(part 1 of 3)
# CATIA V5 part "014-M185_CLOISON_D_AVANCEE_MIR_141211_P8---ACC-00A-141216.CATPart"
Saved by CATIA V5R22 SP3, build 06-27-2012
Part number: Part3
Material "000000011370;Designation TOLE ACIER E390D 1,47MM G10/10;Nuance E390D;Norme Nuance B53 3312;": density 7820 kg/m3
Bounding box of the stored display mesh (mm): x -949.305 to -599.625, y 203.047 to 409.027, z -41.159 to 655.763
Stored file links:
  C:\Users\sys02\Desktop\piese D\014-M185_CLOISON_D_AVANCEE_MIR_141211_P8---ACC-00A-141216.CATPart
  Y:\SICA\141120_P8\Mxxx_CLOISON_D_RECULEE_MIR_141210_P8.CATPart
  G:\P8\envi\K1.BV2SR-.K3D.9675018780.01.SUP-D-TRA-FAC-BLO-AV.----0010CAT.CATPart
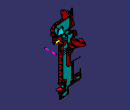
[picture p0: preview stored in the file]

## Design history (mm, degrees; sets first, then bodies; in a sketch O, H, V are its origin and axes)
StDynAnalysisRootNodeFeature1 "CATStDynAnalysisRootNodeName"
Set1 "Draft directions"
  Line1: stored without definition
  Line2: stored without definition
  DatumPoint1 to DatumPoint4
Set2 "ENV HARD"
  DatumSurface1 "--.------.---.AA37605354.--.P87-MS--------------.----0003CAT"
  DatumSurface2 "Y1.BV2SR-.R1A.981031218A.AZ.SYS-ABS-CHO-AVSUPASS.----0002CAT"
  DatumSurface3 "K1.BV2SR-.K3D.9675018780.01.SUP-D-TRA-FAC-BLO-AV.----0010CAT"
  DatumSurface4 "K686_87.BV2AM-.B12.9807801080.00.RADIATEUR-REFROIDISS.----0000CAT_PSA_140623_P8.CATPART"
  DatumSurface5 "L131_AU.P84SR-.K2E.9810619980.00.DEFLECTEUR-AIR-CENT-.----0010CAT_PSA_140826_P8"
  DatumSurface6 "L366_5155275_AU.P84SR-.R1A.981086827A.A..GRIL-SUP-PARE-CHO-AV.----0004CAT_PSA_140922_P8"
  DatumSurface7 "L624_AU.P84SR-.R1A.9811359480.00.CONARPRIAIRDPARCHOAV.----0005CAT_PSA_141013_P8.CATPART"
  DatumSurface8 "L645_AU.P84SR-.R1A.9810866880.00.ARMA-INF-PARE-CHO-AV.----0008CAT_PSA_141014_P8.CATPART"
  DatumSurface9 "L851_AU.P84SR-.K3D.9812138680.00.TRAVER-FACAD-BLOC-AV.----0006CAT_PSA_141104_P8.CATPART"
  DatumSurface10 "L851_AU.P84SR-.R1A.9810634680.00.ARMA-PARE-CHO-AV-ASS.----0004CAT_PSA_141104_P8.CATPART"
  DatumSurface11 "M150_5261904_--.------.---.AA37543391.--.P8X-FONDS-CALANDRES-.----0000CAT"
  DatumSurface12 "M150_5261913_PC AV P84_PSA_141209_P8-PART1"
  DatumSurface13 "M150_5261913_PC AV P84_PSA_141209_P8-PART2"
  DatumSurface14 "M150_5261913_PC AV P84_PSA_141209_P8-PART3"
  DatumSurface15 "L131_AU.P84SR-.K2E.9811450080.00.DEFLECTEUR-AIR-CENT-.----0007CAT_PSA_140826_P8"
  DatumSurface16 "--.------.---.AA37354130.FL.COMP-COND-SANS-CAPA-.----0001CAT"
  DatumSurface17 "K686_--.------.V5D.981046768A.A..TUYAU-REFRIGERAT-ENS.AA37308823.FL.----0000CAT_PSA_140623_P8.CATPART"
Set3 "CONSTRUCTION"
  Set4 "A FACE SOFT MATERIAL"
    Join1: Elements Fillet73
    Intersect1: ToIntersect1 Chamfer3, ToIntersect2 Join1
    Offset1: Offset Chamfer3, Length 6.5
    Intersect2: ToIntersect1 Offset1, ToIntersect2 Join1
    Line3: type PtPt, FirstPoint vertex [face of Intersect2 | face of Intersect2], SecondPoint vertex [face of Intersect2 | face of Intersect2], Start 19, End 20
    Sweep1: type Segment, GuideCrv Line3, Length1 80, Length2 20, Angle 60, DraftDirection Line1
    Line4: type PtPt, FirstPoint vertex [face of Intersect2 | face of Intersect2], SecondPoint vertex [face of Intersect2 | face of Intersect2], Start 43, End 71
    Sweep2: type Segment, GuideCrv Line4, Length1 80, Length2 20, Angle 45, DraftDirection Line1
    Trim1: Trimmed (Sweep2; Sweep1)
    Line5: type PtPt, FirstPoint vertex [face of Intersect2 | face of Intersect2], SecondPoint vertex [face of Intersect2 | face of Intersect2], Start 34, End 30
    Sweep3: type Segment, GuideCrv Line5, Length1 80, Length2 20, Angle 60, DraftDirection Line1
    Split1: ToCut Join1, Cutting Intersect2
    Extrapol1: ToExtrapol edge of Sweep2, Support Trim1, Length 50
    Split2: ToCut Sweep3, Cutting Extrapol1
    Split3: ToCut Split2, Cutting Line5
    MultiExtract1: ListOfMultiExtractConstraints (MultiExtractConstraint edge of Intersect2; MultiExtractConstraint edge of Intersect2; MultiExtractConstraint edge of Split2)
    Split4: ToCut Extrapol1, Cutting MultiExtract1
    Extrapol2: ToExtrapol edge of Sweep1, Support Split4, Length 50
    Line6: type PtPt, FirstPoint vertex [face of Intersect2 | face of Intersect2], SecondPoint vertex [face of Intersect2 | face of Intersect2], Start 24, End 42
    Sweep4: type Segment, GuideCrv Line6, Length1 80, Length2 20, Angle 30, DraftDirection Line1
    Line7: type PtPt, FirstPoint vertex [face of Intersect2 | face of Intersect2], SecondPoint vertex [face of Intersect2 | face of Intersect2], Start 28, End 37
    Sweep5: type Segment, GuideCrv Line7, Length1 80, Length2 20, Angle 60, DraftDirection Line1
    Trim2: Trimmed (Sweep4; Extrapol2)
    Trim3: Trimmed (Sweep5; Trim2)
    Line8: type PtPt, FirstPoint vertex [face of Fillet62 | face of Fillet62], SecondPoint {point type OnCurve, Support edge of Split1, Ratio 0.21}
    Sweep6: type Segment, GuideCrv Line8, Length1 80, Length2 20, Angle 60, DraftDirection Line1
    Extrapol3: ToExtrapol edge of Sweep6, Support Sweep6, Length 50
    Extrapol4: ToExtrapol edge of Sweep6, Support Extrapol3, Length 50
    Line9: type PtPt, FirstPoint {point type OnCurve, Support edge of Split1, Ratio 0.21}, SecondPoint vertex [face of DatumSurface30], Start 54, End 74
    Sweep7: type Segment, GuideCrv Line9, Length1 80, Length2 20, Angle 60, DraftDirection Line1
    Trim4: Trimmed (Sweep7; Extrapol4)
    Fillet1: radius 30, on edge [face of Sweep7 | face of Sweep6]
    Sweep8: type Segment, GuideCrv edge of Split1, Length1 120, Length2 20, Angle 60, DraftDirection Line1
    Extrapol5: ToExtrapol edge of Sweep8, Support Sweep8, Length 80
    Trim5: Trimmed (Fillet1; Extrapol5)
    Fillet2: radius 15, on edge [face of Sweep7 | face of Sweep8]
    Extrapol6: ToExtrapol edge of Sweep8, Support Fillet2, Length 20
    Sweep9: type Segment, GuideCrv edge of Split1, Length1 120, Length2 20, Angle 60, DraftDirection Line1
    Extrapol7: ToExtrapol edge of Sweep9, Support Sweep9, Length 30
    Extrapol8: ToExtrapol edge of Sweep9, Support Extrapol7, Length 30
    Trim6: Trimmed (Extrapol6; Extrapol8)
    Fillet3: radius 15, on edge [face of Sweep8 | face of Sweep9]
    Sweep10: type Segment, GuideCrv edge of Split1, Length1 80, Length2 20, Angle 60, DraftDirection Line1
    Extrapol9: ToExtrapol edge of Sweep10, Support Sweep10, Length 45
    Extrapol10: ToExtrapol edge of Sweep9, Support Fillet3, Length 30
    Trim7: Trimmed (Extrapol10; Extrapol9)
    Fillet4: radius 10, on edge [face of Sweep9 | face of Sweep10]
    Sweep11: type Segment, GuideCrv edge of Split1, Length1 80, Length2 20, Angle 60, DraftDirection Line1
    Sweep12: type Segment, GuideCrv edge of Split1, Length1 80, Length2 20, Angle 45, DraftDirection Line1
    Offset2: Offset Sweep12, Length 11
    Extrapol11: ToExtrapol edge of Sweep10, Support Fillet4, Length 45
    Extrapol12: ToExtrapol edge of Offset2, Support Offset2, Length 45
    Extrapol13: ToExtrapol edge of Offset2, Support Extrapol12, Length 45
    Split5: ToCut Extrapol11, Cutting Extrapol13
    Split6: ToCut Extrapol13, Cutting Split5
    Extrapol14: ToExtrapol edge of Sweep11, Support Sweep11, Length 45
    Split7: ToCut Extrapol14, Cutting Split6
    Split8: ToCut Split6, Cutting Split7
    Extrapol15: ToExtrapol edge of Sweep11, Support Split7, Length 45
    Sweep13: type Segment, GuideCrv edge of Split1, Length1 80, Length2 20, Angle 55, DraftDirection Line1
    Extrapol16: ToExtrapol edge of Sweep13, Support Sweep13, Length 60
    Trim8: Trimmed (Extrapol16; Extrapol15)
    Fillet5: radius 10, on edge [face of Sweep11 | face of Sweep13]
    Extrapol17: ToExtrapol edge of Sweep13, Support Fillet5, Length 60
    Sweep14: type Segment, GuideCrv edge of Split1, Length1 80, Length2 20, Angle 35, DraftDirection Line1
    Extrapol18: ToExtrapol edge of Sweep14, Support Sweep14, Length 60
    Extrapol19: ToExtrapol edge of Sweep14, Support Extrapol18, Length 60
    Trim9: Trimmed (Extrapol19; Extrapol17)
    Fillet6: radius 20, on edge [face of Sweep14 | face of Sweep13]
    Sweep15: type Segment, GuideCrv edge of Split1, Length1 80, Length2 20, Angle 60, DraftDirection Line1
    Extrapol20: ToExtrapol edge of Sweep15, Support Sweep15, Length 60
    Trim10: Trimmed (Extrapol20; Fillet6)
    Fillet7: on edge [face of Sweep15 | face of Sweep14]
    Sweep16: type Segment, GuideCrv edge of Split1, Length1 80, Length2 20, Angle 60, DraftDirection Line1
    Extrapol21: ToExtrapol edge of Sweep16, Support Sweep16, Length 60
    Extrapol22: ToExtrapol edge of Sweep16, Support Extrapol21, Length 60
    Trim11: Trimmed (Extrapol22; Split3)
    Chamfer1: length 29, second length 21, on edge [face of Sweep16 | face of Sweep3]
    Fillet8: on edge [face of Chamfer1 | face of Sweep3]
    Fillet9: on edge [face of Sweep16 | face of Chamfer1]
    Sweep17: type Segment, GuideCrv edge of Split1, Length1 80, Length2 20, Angle 45, DraftDirection Line1
    Extrapol23: ToExtrapol edge of Sweep17, Support Sweep17, Length 60
    Extrapol24: ToExtrapol edge of Sweep17, Support Extrapol23, Length 60
    Trim12: Trimmed (Fillet9; Extrapol24)
    Fillet10: on edge [face of Sweep17 | face of Sweep16]
    Sweep18: type Segment, GuideCrv edge of Split1, Length1 80, Length2 20, Angle 50, DraftDirection Line1
    Sweep19: type Segment, GuideCrv edge of Split1, Length1 80, Length2 20, Angle 50, DraftDirection Line1
    Blend1: StartLimit {blendlimit Curve edge of Sweep18}, EndLimit {blendlimit Curve edge of Sweep19}
    Join2: Elements (Blend1; Sweep19; Sweep18)
    Extrapol25: ToExtrapol edge of Sweep18, Support Join2, Length 60
    Trim13: Trimmed (Fillet10; Extrapol25)
    Fillet11: on edge [face of Sweep18 | face of Sweep17]
    Fillet12: on edge [face of Blend1 | face of Sweep18]
    Fillet13: on edge [face of Sweep19 | face of Blend1]
    Extrapol26: ToExtrapol edge of Sweep19, Support Fillet13, Length 60
    Sweep20: type Segment, GuideCrv edge of Split1, Length1 80, Length2 20, Angle 7, DraftDirection Line1
    Extrapol27: ToExtrapol edge of Sweep20, Support Sweep20, Length 60
    Extrapol28: ToExtrapol edge of Sweep20, Support Extrapol27, Length 60
    Trim14: Trimmed (Extrapol26; Extrapol28)
    Fillet14: on edge [face of Sweep19 | face of Sweep20]
    Sweep21: type Segment, GuideCrv edge of Split1, Length1 80, Length2 20, Angle 45, DraftDirection Line1
    Extrapol29: ToExtrapol edge of Sweep21, Support Sweep21, Length 60
    Extrapol30: ToExtrapol edge of Sweep21, Support Extrapol29, Length 60
    Trim15: Trimmed (Fillet14; Extrapol30)
    Fillet15: on edge [face of Sweep20 | face of Sweep21]
    Sweep22: type Segment, GuideCrv edge of Split1, Length1 80, Length2 20, Angle 45, DraftDirection Line1
    Extrapol31: ToExtrapol edge of Sweep22, Support Sweep22, Length 60
    Trim16: Trimmed (Fillet15; Extrapol31)
    Fillet16: on edge [face of Sweep21 | face of Sweep22]
    Sweep23: type Segment, GuideCrv edge of Split1, Length1 80, Length2 20, Angle 45, DraftDirection Line1
    Blend2: StartLimit {blendlimit Curve edge of Sweep23}, EndLimit {blendlimit Curve edge of Sweep22}
    Join3: Elements (Fillet16; Blend2; Sweep23)
    Fillet17: on edge [face of Sweep23 | face of Blend2]
    Fillet18: on edge [face of Blend2 | face of Sweep22]
    Extrapol32: ToExtrapol edge of Sweep23, Support Fillet18, Length 15
    Sweep24: type Segment, GuideCrv edge of Split1, Length1 80, Length2 20, Angle 7, DraftDirection Line1
    Extrapol33: ToExtrapol edge of Offset43, Support {inverselocal InverseElem Offset43}, Length 55
    Trim17: Trimmed (Extrapol32; Extrapol33)
    Fillet19: on edge [face of Sweep23 | face of Offset43]
    Extrapol34: ToExtrapol edge of Offset43, Support Fillet19, Length 10
    Offset3: Offset Sweep74, Length 0
    Sweep25: type Segment, GuideCrv edge of Split1, Length1 80, Length2 20, Angle 7, DraftDirection Line1
    Extrapol35: ToExtrapol edge of Sweep25, Support Sweep25, Length 150
    Extrapol36: ToExtrapol edge of Sweep15, Support Fillet7, Length 100
    Extrapol37: ToExtrapol edge of Sweep25, Support Extrapol35, Length 30
    Trim18: Trimmed (Extrapol37; Extrapol36)
    Extrapol38: ToExtrapol edge of Sweep25, Support Trim18, Length 30
    Trim19: Trimmed (Sweep72; Extrapol38)
    Sweep26: type Segment, GuideCrv edge of Split1, Length1 80, Length2 20, Angle 7, DraftDirection Line1
    Extrapol39: ToExtrapol edge of Sweep26, Support Sweep26, Length 100
    Trim20: Trimmed (Trim19; Extrapol39)
    Sweep27: type Segment, GuideCrv edge of Split1, Length1 80, Length2 20, Angle 30, DraftDirection Line1
    Extrapol40: ToExtrapol edge of Sweep27, Support Sweep27, Length 110
    Extrapol41: ToExtrapol edge of Sweep27, Support Extrapol40, Length 60
    Trim21: Trimmed (Trim20; Extrapol41)
    Line10: stored without definition
    Sweep28: type Segment, GuideCrv Line10, Length1 80, Length2 20, Angle 7, DraftDirection Line1
    Extrapol42: ToExtrapol edge of Offset42, Support {inverselocal InverseElem Offset42}, Length 20
    Extrapol43: ToExtrapol edge of Offset42, Support Extrapol42, Length 60
    CurvePar1: Offset edge of Offset3, Support Offset3, Offset2 0, Offset1 22
    Split9: ToCut Offset3, Cutting CurvePar1
    Trim22: Trimmed (Split9; Extrapol34)
    Trim23: Trimmed (Trim22; Extrapol43)
    Trim24: Trimmed (Trim23; Trim21)
    Extrapol44: ToExtrapol edge of Split6, Support Split8, Length 60
    Split10: ToCut Extrapol44, Cutting Join1
    Extrapol45: ToExtrapol edge of Split4, Support Trim3, Length 60
    Fillet20: radius 10, on edge [face of Sweep1 | face of Sweep4]
    Fillet21: radius 10, on edge [face of Fillet20 | face of Sweep5]
    Trim25: Trimmed (Fillet21; Split5)
    Fillet22: radius 10, on edge [face of Sweep5 | face of Sweep6]
    Split11: ToCut Trim24, Cutting Join1
    Fillet23: type BiTangent, Element1 Split8, Element2 Fillet22, Radius 10
    Extrapol46: ToExtrapol edge of Extrapol44, Support Split10, Length 60
    Split12: ToCut Extrapol46, Cutting edge [face of Fillet23 | face of Offset2]
    Intersect3: ToIntersect1 Join1, ToIntersect2 Split11
    Intersect4: ToIntersect1 Join1, ToIntersect2 Fillet23
    Extract1: ExtractElem edge of Intersect4
    Trim26: Trimmed (edge of Split10; Extract1)
    Split13: ToCut Trim26, Cutting vertex of Intersect3
    Join4: Elements (Split13; Intersect3)
    Split14: ToCut Join1, Cutting Join4
    Trim27: Trimmed (edge of Split12; Split13)
    Split15: ToCut Fillet23, Cutting Trim27
    Join5: Elements (Split15; Split12; Split11; Split14)
    Fillet24: radius 20, on edge [face of Offset2 | face of Sweep11]
    Fillet25: radius 5.8, on edge [face of DatumSurface34 | face of Sweep13]
    Fillet26: radius 10, on edge [face of Sweep26 | face of Sweep27]
    Fillet27: radius 10, on edge [face of Offset42 | face of Sweep27]
    Fillet28: radius 15, on edge [face of Sweep2 | face of Sweep1]
    Fillet29: radius 4.8, on edge [face of Sweep3 | face of DatumSurface25]
    Fillet30: radius 6.8, on edge [face of Sweep27 | face of DatumSurface25]
    Fillet31: radius 6.8, on edge [face of Sweep25 | face of DatumSurface27]
    Fillet32: radius 5.5, on edge [face of Sweep8 | face of DatumSurface30]
    Join6: Elements Fillet32, SubElementsToRemove face of Sweep6
    Curve1: Elements (vertex [face of Fillet22 | face of Sweep1]; vertex [face of Sweep1 | face of Fillet28]), Support Join6
    Split16: ToCut Join6, Cutting Curve1
    Extrapol47: ToExtrapol edge of Sweep25, Support Extrapol37, Length 50
    Extrapol48: ToExtrapol edge of Sweep48, Support Sweep48, Length 50
  Set5 "LIMITS SOFT"
    MultiExtract2: ListOfMultiExtractConstraints MultiExtractConstraint face of DatumSurface4
    Extrapol49: ToExtrapol edge of MultiExtract2, Support MultiExtract2, Length 170
    Extrapol50: ToExtrapol edge of MultiExtract2, Support Extrapol49, Length 210
    Offset4: Offset Extrapol50, Length 5
    Extrapol51: ToExtrapol edge of Offset4, Support Offset4, Length 65
    MultiExtract3: ListOfMultiExtractConstraints MultiExtractConstraint face of DatumSurface15
    StUntrimFeature1 "CATStUntrimFeatureName": SpecToUntrim MultiExtract3
    Extrapol52: ToExtrapol edge of StUntrimFeature1, Support StUntrimFeature1, Length 170
    Offset5: Offset Extrapol52, Length 5
    MultiExtract4: ListOfMultiExtractConstraints MultiExtractConstraint face of DatumSurface8
    MultiExtract5: ListOfMultiExtractConstraints MultiExtractConstraint face of DatumSurface8
    MultiExtract6: ListOfMultiExtractConstraints MultiExtractConstraint face of DatumSurface8
    Extrapol53: ToExtrapol edge of MultiExtract5, Support MultiExtract5, Length 50
    Offset6: Offset Extrapol53, Length 5
    Extrapol54: ToExtrapol edge of MultiExtract4, Support MultiExtract4, Length 50
    Offset7: Offset Extrapol54, Length 5
    Extrapol55: ToExtrapol edge of MultiExtract6, Support MultiExtract6, Length 50
    Offset8: Offset Extrapol55, Length 5
    CurvePar2: Offset edge of Offset8, Support Offset8, Offset2 0, Offset1 115
    CurvePar3: Offset edge of Offset6, Support Offset6, Offset2 0, Offset1 111
    Sweep29: type Segment, GuideCrv CurvePar3, Length1 120, Length2 20, Angle 7, DraftDirection Line1
    Sweep30: type Segment, GuideCrv CurvePar2, Length1 120, Length2 20, Angle 7, DraftDirection Line1
    Trim28: Trimmed (Sweep30; Offset7)
    Trim29: Trimmed (Offset5; Sweep29)
    Trim30: Trimmed (Trim28; Trim29)
    MultiExtract7: ListOfMultiExtractConstraints MultiExtractConstraint face of DatumSurface14
    StUntrimFeature2 "CATStUntrimFeatureName": SpecToUntrim MultiExtract7
    Extrapol56: ToExtrapol edge of StUntrimFeature2, Support StUntrimFeature2, Length 79
    Extrapol57: ToExtrapol edge of StUntrimFeature2, Support Extrapol56, Length 79
    Extrapol58: ToExtrapol edge of StUntrimFeature2, Support Extrapol57, Length 79
    Trim31: Trimmed (Extrapol58; Trim30)
    MultiExtract8: ListOfMultiExtractConstraints MultiExtractConstraint face of DatumSurface15
    Sweep31: type Segment, GuideCrv edge of MultiExtract8, Length1 120, Length2 20, Angle 5, DraftDirection (0, 0, 1)
    Sweep32: type Segment, GuideCrv edge of MultiExtract8, Length1 120, Length2 20, Angle 5, DraftDirection (0, 0, 1)
    Sweep33: type Segment, GuideCrv edge of Sweep31, Length1 120, Length2 20, Angle 10, DraftDirection Line1
    Sweep34: type Segment, GuideCrv edge of Sweep32, Length1 120, Length2 20, Angle 7, DraftDirection Line1
    Offset9: Offset Sweep33, Length 5
    Offset10: Offset Sweep34, Length 7
    Extrapol59: ToExtrapol edge of Offset10, Support Offset10, Length 79
    Extrapol60: ToExtrapol edge of Offset9, Support Offset9, Length 79
    StUntrimFeature3 "CATStUntrimFeatureName": SpecToUntrim MultiExtract8
    Offset11: Offset StUntrimFeature3, Length 1
    Trim32: Trimmed (Extrapol59; Offset11)
    Trim33: Trimmed (Trim32; Extrapol60)
    MultiExtract9: ListOfMultiExtractConstraints MultiExtractConstraint face of DatumSurface13
    StUntrimFeature4 "CATStUntrimFeatureName": SpecToUntrim MultiExtract9
    Extrapol61: ToExtrapol edge of StUntrimFeature4, Support StUntrimFeature4, Length 79
    Offset12: Offset Extrapol61, Length 5
    Extrapol62: ToExtrapol edge of Offset12, Support Offset12, Length 79
    MultiExtract10: ListOfMultiExtractConstraints (MultiExtractConstraint face of DatumSurface10; MultiExtractConstraint face of DatumSurface10; MultiExtractConstraint face of DatumSurface10)
    Extrapol63: ToExtrapol edge of MultiExtract10, Support MultiExtract10, Length 10
    Extrapol64: ToExtrapol edge of MultiExtract10, Support Extrapol63, Length 10
    Offset13: Offset Extrapol64, Length 5
    Split17: ToCut Offset13, Cutting edge [face of Offset13 | face of Offset13]
    Plane1: type Normal, Curve edge of Offset13, RefPoint vertex [face of Offset13]
    Extrapol65: ToExtrapol edge of Offset13, Support Split17, Length 50
    Extrapol66: ToExtrapol edge of Offset13, Support {split ToCut Offset13, Cutting edge [face of Offset13 | face of Offset13]}, Length 50
    Trim34: Trimmed (Extrapol66; Extrapol65)
    Trim35: Trimmed (Extrapol62; Trim34)
    Extrapol67: ToExtrapol edge of Offset13, Support Trim35, Length 100
    MultiExtract11: ListOfMultiExtractConstraints (MultiExtractConstraint face of DatumSurface10; MultiExtractConstraint face of DatumSurface10; MultiExtractConstraint face of DatumSurface10; MultiExtractConstraint face of DatumSurface10; MultiExtractConstraint face of DatumSurface10; MultiExtractConstraint face of DatumSurface10)
    Offset14: Offset MultiExtract11, Length 5
    Extrapol68: ToExtrapol edge of Offset14, Support Offset14, Length 100
    Extrapol69: ToExtrapol edge of Offset14, Support Extrapol68, Length 100
    Plane2: type Normal, Curve edge [face of Offset14 | face of Offset14]
    Split18: ToCut Extrapol69, Cutting Plane2
    Plane3: type Offset, RefPlane Plane2, Offset -11
    Split19: ToCut Split18, Cutting Plane3
    Extract2: ExtractElem face of Offset14
    Extrapol70: ToExtrapol edge of Split19, Support Extract2, Length 100
    Extrapol71: ToExtrapol edge of Split19, Support Extrapol70, Length 100
    Extrapol72: ToExtrapol edge of Split19, Support Extrapol71, Length 100
    Extrapol73: ToExtrapol edge of Offset14, Support Extrapol72, Length 100
    MultiExtract12: ListOfMultiExtractConstraints MultiExtractConstraint face of DatumSurface4
    StUntrimFeature5 "CATStUntrimFeatureName": SpecToUntrim MultiExtract12
    Extrapol74: ToExtrapol edge of StUntrimFeature5, Support StUntrimFeature5, Length 15
    Extrapol75: ToExtrapol edge of StUntrimFeature5, Support Extrapol74, Length 150
    Offset15: Offset Extrapol75, Length 3
    MultiExtract13: ListOfMultiExtractConstraints MultiExtractConstraint face of DatumSurface4
    StUntrimFeature6 "CATStUntrimFeatureName": SpecToUntrim MultiExtract13
    MultiExtract14: ListOfMultiExtractConstraints MultiExtractConstraint face of DatumSurface4
    StUntrimFeature7 "CATStUntrimFeatureName": SpecToUntrim MultiExtract14
    Extrapol76: ToExtrapol edge of StUntrimFeature7, Support StUntrimFeature7, Length 150
    Extrapol77: ToExtrapol edge of StUntrimFeature7, Support Extrapol76, Length 150
    Extrapol78: ToExtrapol edge of StUntrimFeature7, Support Extrapol77, Length 10
    Extrapol79: ToExtrapol edge of StUntrimFeature7, Support Extrapol78, Length 10
    Offset16: Offset Extrapol79, Length 3
    MultiExtract15: ListOfMultiExtractConstraints (MultiExtractConstraint face of DatumSurface7; MultiExtractConstraint face of DatumSurface7; MultiExtractConstraint face of DatumSurface7; MultiExtractConstraint face of DatumSurface7; MultiExtractConstraint face of DatumSurface7)
    Offset17: Offset MultiExtract15, Length 5
    Extrapol80: ToExtrapol edge of Offset17, Support Offset17, Length 50
    Extrapol81: ToExtrapol edge of Offset17, Support Extrapol80, Length 50
    Extrapol82: ToExtrapol edge of Offset17, Support Extrapol81, Length 50
    Extrapol83: ToExtrapol edge of Offset17, Support Extrapol82, Length 50
    Intersect5: ToIntersect1 Extrapol83, ToIntersect2 Split16
    Sweep35: type Segment, GuideCrv Intersect5, GuideSurf Split16, Length1 6, Length2 6, Angle 90
    Split20: ToCut Sweep35, Cutting edge [face of Sweep35 | face of Sweep35]
    Split21: ToCut {split ToCut Sweep35, Cutting edge [face of Sweep35 | face of Sweep35]}, Cutting edge [face of Sweep35 | face of Sweep35]
    Extrapol84: ToExtrapol edge of Split21, Support Split21, Length 50
    Extrapol85: ToExtrapol edge of Split20, Support Split20, Length 50
    Extrapol86: ToExtrapol edge of Sweep35, Support Extrapol85, Length 10
    Trim36: Trimmed (Extrapol86; Extrapol84)
    Fillet33: radius 20, on edge [face of Sweep35 | face of Sweep35]
    Split22: ToCut Fillet33, Cutting edge [face of Sweep35 | face of Sweep35]
    Split23: ToCut {split ToCut Fillet33, Cutting edge [face of Sweep35 | face of Sweep35]}, Cutting edge [face of Sweep35 | face of Sweep35]
    Extrapol87: ToExtrapol edge of Split22, Support Split22, Length 38
    Extrapol88: ToExtrapol edge of Sweep35, Support Extrapol87, Length 15
    Blend3: StartLimit {blendlimit Curve edge of Split22, Support Extrapol88, TensionValues 1}, EndLimit {blendlimit Curve edge of Split23, Support Split23, TensionValues 1}
    Split24: ToCut Split23, Cutting edge [face of Sweep35 | face of Sweep35]
    Blend4: StartLimit {blendlimit Curve edge of Split24, Support Split24, TensionValues 1}, EndLimit {blendlimit Curve edge of Blend3, Support Blend3, TensionValues 1}
    Join7: Elements (Blend3; Extrapol88; Blend4; Split24)
    Extrapol89: ToExtrapol edge of Sweep35, Support Join7, Length 15
    MultiExtract16: ListOfMultiExtractConstraints MultiExtractConstraint face of DatumSurface2
    MultiExtract17: ListOfMultiExtractConstraints MultiExtractConstraint face of DatumSurface2
    MultiExtract18: ListOfMultiExtractConstraints MultiExtractConstraint face of DatumSurface2
    MultiExtract19: ListOfMultiExtractConstraints MultiExtractConstraint face of DatumSurface2
    MultiExtract20: ListOfMultiExtractConstraints MultiExtractConstraint face of DatumSurface2
    StUntrimFeature8 "CATStUntrimFeatureName": SpecToUntrim MultiExtract19
    StUntrimFeature9 "CATStUntrimFeatureName": SpecToUntrim MultiExtract20
    StUntrimFeature10 "CATStUntrimFeatureName": SpecToUntrim MultiExtract18
    Extrapol90: ToExtrapol edge of StUntrimFeature10, Support StUntrimFeature10, Length 100
    Extrapol91: ToExtrapol edge of StUntrimFeature9, Support StUntrimFeature9, Length 160
    Extrapol92: ToExtrapol edge of StUntrimFeature8, Support StUntrimFeature8, Length 130
    Trim37: Trimmed (Extrapol92; Extrapol91)
    Trim38: Trimmed (Trim37; Extrapol90)
    Offset18: Offset Trim38, Length 5
    MultiExtract21: ListOfMultiExtractConstraints (MultiExtractConstraint face of DatumSurface6; MultiExtractConstraint face of DatumSurface6; MultiExtractConstraint face of DatumSurface6; MultiExtractConstraint face of DatumSurface6; MultiExtractConstraint face of DatumSurface6; MultiExtractConstraint face of DatumSurface6; MultiExtractConstraint face of DatumSurface6; MultiExtractConstraint face of DatumSurface6; MultiExtractConstraint face of DatumSurface6; MultiExtractConstraint face of DatumSurface6; MultiExtractConstraint face of DatumSurface6)
    Offset19: Offset MultiExtract21, Length 5, TrickyFaces (face of DatumSurface6; face of DatumSurface6)
    Fillet34: radius 5, on edge [face of Offset19 | face of Offset19]
    FaceFillet1: ConicRatio 0.5, Face1 face of Offset19, Face2 face of Offset19, Radius 5
    Extrapol93: ToExtrapol edge of Offset19, Support FaceFillet1, Length 20
    Extrapol94: ToExtrapol edge of Offset19, Support Extrapol93, Length 20
    Extrapol95: ToExtrapol edge of Offset19, Support Extrapol94, Length 50
    Extrapol96: ToExtrapol edge of Offset19, Support Extrapol95, Length 50
    Intersect6: ToIntersect1 Extrapol96, ToIntersect2 Split16
    Sweep36: type Segment, GuideCrv Intersect6, GuideSurf Split16, Length1 3, Length2 3, Angle 90
    Extrapol97: ToExtrapol edge of Sweep36, Support Sweep36, Length 20
    Extrapol98: ToExtrapol edge of Sweep36, Support Extrapol97, Length 50
    MultiExtract22: ListOfMultiExtractConstraints MultiExtractConstraint face of DatumSurface10
    MultiExtract23: ListOfMultiExtractConstraints MultiExtractConstraint face of DatumSurface10
    StUntrimFeature11 "CATStUntrimFeatureName": SpecToUntrim MultiExtract22
    StUntrimFeature12 "CATStUntrimFeatureName": SpecToUntrim MultiExtract23
    Extrapol99: ToExtrapol edge of StUntrimFeature12, Support StUntrimFeature12, Length 50
    Extrapol100: ToExtrapol edge of StUntrimFeature11, Support StUntrimFeature11, Length 120
    Offset20: Offset Extrapol100, Length 5
    Offset21: Offset Extrapol99, Length 5
    Trim39: Trimmed (Offset20; Offset21)
    MultiExtract24: ListOfMultiExtractConstraints MultiExtractConstraint face of DatumSurface10
    StUntrimFeature13 "CATStUntrimFeatureName": SpecToUntrim MultiExtract24
    Extrapol101: ToExtrapol edge of StUntrimFeature13, Support StUntrimFeature13, Length 120
    Offset22: Offset Extrapol101, Length 5
    MultiExtract25: ListOfMultiExtractConstraints MultiExtractConstraint face of DatumSurface9
    MultiExtract26: ListOfMultiExtractConstraints MultiExtractConstraint face of DatumSurface9
    MultiExtract27: ListOfMultiExtractConstraints MultiExtractConstraint face of DatumSurface9
    MultiExtract28: ListOfMultiExtractConstraints MultiExtractConstraint face of DatumSurface9
    MultiExtract29: ListOfMultiExtractConstraints MultiExtractConstraint face of DatumSurface9
    StUntrimFeature14 "CATStUntrimFeatureName": SpecToUntrim MultiExtract25
    StUntrimFeature15 "CATStUntrimFeatureName": SpecToUntrim MultiExtract26
    StUntrimFeature16 "CATStUntrimFeatureName": SpecToUntrim MultiExtract27
    StUntrimFeature17 "CATStUntrimFeatureName": SpecToUntrim MultiExtract28
    StUntrimFeature18 "CATStUntrimFeatureName": SpecToUntrim MultiExtract29
    Extrapol102: ToExtrapol edge of StUntrimFeature18, Support StUntrimFeature18, Length 50
    Extrapol103: ToExtrapol edge of StUntrimFeature17, Support StUntrimFeature17, Length 50
    Extrapol104: ToExtrapol edge of StUntrimFeature15, Support StUntrimFeature15, Length 50
    Extrapol105: ToExtrapol edge of StUntrimFeature14, Support StUntrimFeature14, Length 50
    Offset23: Offset Extrapol105, Length 5
    Offset24: Offset Extrapol104, Length -4
    Trim40: Trimmed (Offset24; Offset23)
    Offset25: Offset Extrapol102, Length 5
    Extrapol106: ToExtrapol edge of Offset25, Support Offset25, Length 50
    Offset26: Offset Extrapol103, Length 5
    Extrapol107: ToExtrapol edge of Offset26, Support Offset26, Length 50
    Offset27: Offset Extrapol103, Length 15
    Extrapol108: ToExtrapol edge of Offset27, Support Offset27, Length 50
    Trim41: Trimmed (Extrapol108; Offset23)
    Trim42: Trimmed (Trim41; Offset24)
    Extrapol109: ToExtrapol edge of Offset25, Support Extrapol106, Length 50
    Trim43: Trimmed (Trim42; Extrapol109)
    Trim44: Trimmed (Offset24; Offset23)
    Trim45: Trimmed (Extrapol107; Trim44)
    Offset28: Offset StUntrimFeature17, Length 5
    Extrapol110: ToExtrapol edge of Offset28, Support Offset28, Length 50
    MultiExtract30: ListOfMultiExtractConstraints MultiExtractConstraint face of DatumSurface9
    Blend5: StartLimit {blendlimit Curve edge of MultiExtract30}, EndLimit {blendlimit Curve edge of MultiExtract30}
    Blend6: StartLimit {blendlimit Curve edge of Blend5}, EndLimit {blendlimit Curve edge of Blend5}
    Plane4: type Tangent, Support Blend6, RefPoint vertex [face of Blend6]
    MultiExtract31: ListOfMultiExtractConstraints MultiExtractConstraint edge of Blend6
    Project1: ToProject MultiExtract31, Support Plane4
    Split25: ToCut Plane4, Cutting Project1
    Extrapol111: ToExtrapol edge of Split25, Support Split25, Length 50
    Offset29: Offset Extrapol111, Length 5
    Trim46: Trimmed (Offset29; Extrapol110)
    MultiExtract32: ListOfMultiExtractConstraints MultiExtractConstraint face of DatumSurface3
    StUntrimFeature19 "CATStUntrimFeatureName": SpecToUntrim MultiExtract32
    Extrapol112: ToExtrapol edge of StUntrimFeature19, Support StUntrimFeature19, Length 50
    Offset30: Offset Extrapol112, Length 5
    Extrapol113: ToExtrapol edge of Offset30, Support Offset30, Length 50
    MultiExtract33: ListOfMultiExtractConstraints MultiExtractConstraint face of DatumSurface14
    MultiExtract34: ListOfMultiExtractConstraints MultiExtractConstraint face of DatumSurface14
    MultiExtract35: ListOfMultiExtractConstraints MultiExtractConstraint face of DatumSurface14
    MultiExtract36: ListOfMultiExtractConstraints MultiExtractConstraint face of DatumSurface14
    StUntrimFeature20 "CATStUntrimFeatureName": SpecToUntrim MultiExtract36
    Extrapol114: ToExtrapol edge of StUntrimFeature20, Support StUntrimFeature20, Length 50
    StUntrimFeature21 "CATStUntrimFeatureName": SpecToUntrim MultiExtract35
    Extrapol115: ToExtrapol edge of StUntrimFeature21, Support StUntrimFeature21, Length 50
    Trim47: Trimmed (Extrapol115; Extrapol114)
    StUntrimFeature22 "CATStUntrimFeatureName": SpecToUntrim MultiExtract34
    Offset31: Offset Trim47, Length 5
    Offset32: Offset StUntrimFeature22, Length 5
    StUntrimFeature23 "CATStUntrimFeatureName": SpecToUntrim Offset32
    Extrapol116: ToExtrapol edge of Offset32, Support Offset32, Length 50
    Trim48: Trimmed (Offset31; Extrapol116)
    Intersect7: ToIntersect1 Sweep30, ToIntersect2 Offset7
    CurvePar4: Offset Intersect7, Support Offset7, Offset2 0, Offset1 17
    Split26: ToCut Offset7, Cutting CurvePar4
    Trim49: Trimmed (Split26; Sweep30)
    MultiExtract37: ListOfMultiExtractConstraints MultiExtractConstraint face of DatumSurface13
    StUntrimFeature24 "CATStUntrimFeatureName": SpecToUntrim MultiExtract37
    Extrapol117: ToExtrapol edge of StUntrimFeature24, Support StUntrimFeature24, Length 30
    Offset33: Offset Extrapol117, Length 5
    MultiExtract38: ListOfMultiExtractConstraints MultiExtractConstraint face of DatumSurface6
    StUntrimFeature25 "CATStUntrimFeatureName": SpecToUntrim MultiExtract38
    Offset34: Offset StUntrimFeature25, Length 5
    Extrapol118: ToExtrapol edge of Offset34, Support Offset34, Length 50
    MultiExtract39: ListOfMultiExtractConstraints MultiExtractConstraint face of Solid1
    StUntrimFeature26 "CATStUntrimFeatureName": SpecToUntrim MultiExtract39
    Extrapol119: ToExtrapol edge of StUntrimFeature26, Support StUntrimFeature26, Length 50
    MultiExtract40: ListOfMultiExtractConstraints (MultiExtractConstraint face of Split76; MultiExtractConstraint face of Solid1; MultiExtractConstraint face of Split75)
    Extrapol120: ToExtrapol edge of MultiExtract40, Support MultiExtract40, Length 1
    Blend7: StartLimit {blendlimit Curve edge of MultiExtract40}, EndLimit {blendlimit Curve edge of MultiExtract40}
    Join8: Elements (Extrapol120; Blend7)
    MultiExtract41: ListOfMultiExtractConstraints MultiExtractConstraint face of Solid2
    StUntrimFeature27 "CATStUntrimFeatureName": SpecToUntrim MultiExtract41
    Extrapol121: ToExtrapol edge of StUntrimFeature27, Support StUntrimFeature27, Length 30
    MultiExtract42: ListOfMultiExtractConstraints (MultiExtractConstraint face of Solid2; MultiExtractConstraint face of Solid2; MultiExtractConstraint face of Solid2)
    Extrapol122: ToExtrapol edge of MultiExtract42, Support MultiExtract42, Length 1
    Blend8: StartLimit {blendlimit Curve edge of MultiExtract42}, EndLimit {blendlimit Curve edge of MultiExtract42}
    Join9: Elements (Blend8; Extrapol122)
    Translate1: ToTransfor Trim51, Direction edge of Sweep37, Length -43
    Extrapol123: ToExtrapol edge of Translate1, Support Translate1, Length 10
    Extrapol124: ToExtrapol edge of Translate1, Support Extrapol123, Length 10
    Extrapol125: ToExtrapol edge of Translate1, Support Extrapol124, Length 10
    Extrapol126: ToExtrapol edge of Translate1, Support Extrapol125, Length 20
  Set6 "CUTOUT"
    Plane5: type Normal, Curve Line1
    Sketch1 on Plane5, origin (0, 255.047, 0), H (-1, 0, 0), V (0, 0, 1)
      line L1 (836.8486, 593.3885) -> (901.0308, 593.3885)
      line L2 (824.9105, 613.9573) -> (853.2032, 636.101)
      construction line L3 (839.8663, 602.7514) -> (881.6075, 630.8052)
      line L4 (791.8511, 640.7266) -> (791.8511, 664.0454)
      line L5 (812.9244, 625.1204) -> (833.1709, 652.6396)
      line L6 (772.5839, 629.9347) -> (741.744, 629.9347)
      line L7 (759.9691, 601.9005) -> (743.7565, 624.3543)
      line L8 (730.2239, 600.2727) -> (730.2239, 623.3475)
      line L9 (703.3942, 600.2962) -> (703.3942, 625.4317)
      line L10 (677.5871, 600.7789) -> (677.5871, 624.3543)
      line L11 (650.9753, 601.9914) -> (650.9753, 624.3543)
      line L12 (623.7806, 601.3758) -> (623.7806, 622.8853)
      construction line L13 (605.4555, 595.8929) -> (566.4078, 612.5472)
      line L14 (607.9188, 582.2664) -> (563.8895, 578.4186)
      construction line L15 (613.7861, 561.4357) -> (567.0342, 558.0362)
      line L16 (621.7963, 541.2258) -> (579.8459, 541.2258)
      line L17 (629.7491, 519.3745) -> (583.1071, 519.3745)
      line L18 (625.9684, 497.1216) -> (590.9108, 485.0086)
      point P36 (590.9108, 485.0086)
      line L19 (646.7529, 494.4061) -> (646.7529, 478.558)
      line L20 (667.9818, 494.0375) -> (667.9818, 480.3271)
      line L21 (690.0217, 491.3102) -> (679.0386, 485.2658)
      line L22 (838.3947, 566.6301) -> (899.1691, 566.6301)
      line L23 (838.3947, 539.6342) -> (898.0839, 539.6342)
      line L24 (837.4451, 513.3167) -> (896.1847, 513.3167)
      line L25 (818.3706, 486.1853) -> (890.894, 486.1853)
      line L26 (848.1837, 458.1259) -> (880.5106, 472.746)
      line L27 (856.306, 435.8707) -> (902.4409, 435.8707)
      line L28 (851.5951, 417.3517) -> (873.4191, 402.3276)
      line L29 (804.0554, 353.1195) -> (837.1854, 306.8726)
      line L30 (829.5524, 368.3177) -> (881.6519, 306.8726)
      line L31 (777.7391, 228.9142) -> (817.8264, 264.1896)
      line L32 (773.3812, 310.4078) -> (814.8228, 310.4078)
      line L33 (816.6197, 194.1951) -> (863.9594, 194.1951)
      line L34 (815.9638, 166.316) -> (865.0532, 166.316)
      line L35 (818.5877, 139.5849) -> (856.0536, 139.5849)
      line L36 (814.9799, 94.6504) -> (848.7353, 113.2748)
      line L37 (866.7767, 81.1821) -> (873.6227, 109.3908)
      line L38 (890.9779, 76.997) -> (898.0055, 105.1707)
      line L39 (907.3546, 57.8908) -> (958.1818, 57.8908)
      line L40 (899.3482, 36.6011) -> (932.5222, -10.6451)
      line L41 (875.5909, 31.8607) -> (875.5909, -18.9278)
      line L42 (825.1822, 36.5625) -> (835.3648, -18.0614)
      line L43 (812.6201, 37.1009) -> (812.6201, 0.9574)
      line L44 (753.4063, -21.8871) -> (757.6756, -52.9355)
      line L45 (736.0044, -24.3563) -> (740.2634, -55.3297)
      line L46 (718.485, -26.5903) -> (722.5731, -56.3217)
      line L47 (696.7797, -30.9215) -> (675.0673, -58.4882)
      line L48 (695.9481, -15.337) -> (663.9949, -15.337)
      line L49 (697.3648, 12.4094) -> (655.604, 12.4094)
      construction line L50 (699.2234, 26.371) -> (683.9081, 37.5549)
      line L51 (705.8117, 122.6048) -> (678.2665, 122.6048)
      line L52 (704.7755, 149.5487) -> (679.3374, 149.5487)
      line L53 (704.7755, 176.7932) -> (676.4954, 176.7932)
      line L54 (704.7755, 203.887) -> (678.6198, 203.887)
      line L55 (704.7755, 230.529) -> (679.3374, 230.529)
      line L56 (704.7755, 257.6231) -> (678.6198, 257.6231)
      line L57 (704.1102, 284.7171) -> (678.6198, 284.7171)
      line L58 (704.1102, 311.1943) -> (677.1845, 311.1943)
      line L59 (702.6399, 338.6045) -> (680.6637, 338.6045)
      line L60 (702.6399, 369.01) -> (680.6637, 369.01)
      line L61 (706.1362, 391.7361) -> (679.9459, 391.7361)
      line L62 (708.2627, 421.5379) -> (688.1135, 432.4358)
      line L63 (839.2587, 233.9259) -> (839.2587, 256.1118)
      line L64 (804.0554, 321.9002) -> (788.5677, 355.6367)
      horizontal: L1 H, L6 H, L16 H, L17 H, L22 H, L23 H, L24 H, L25 H, L27 H, L32 H, L33 H, L34 H, L35 H, L39 H, L48 H, L49 H, L51 H, L52 H, L53 H, L54 H, L55 H, L56 H, L57 H, L58 H, L59 H, L60 H, L61 H
      vertical: L4 V, L8 V, L9 V, L10 V, L11 V, L12 V, L19 V, L20 V, L41 V, L43 V, L63 V
      parallelism: L45 L44, L46 L45
      coincidence: L62 P36
      fix: L25
    Offset35: Offset Split16, Length 0.25
    Offset36: Offset Split16, Length 2
    DatumSurface18
    Extrapol127: ToExtrapol edge of DatumSurface18, Support DatumSurface18, Length 1
    Join10: Elements Extrapol127, SubElementsToRemove (face of DatumSurface18; face of DatumSurface18)
    Join11: Elements Join10, SubElementsToRemove (face of DatumSurface18; face of DatumSurface18)
    MultiExtract43: ListOfMultiExtractConstraints MultiExtractConstraint edge of DatumSurface18
    Sweep37: type Segment, GuideCrv MultiExtract43, Length1 3, Length2 3, Angle 3, DraftDirection Line1
    MultiExtract44: ListOfMultiExtractConstraints MultiExtractConstraint edge of DatumSurface18
    MultiExtract45: ListOfMultiExtractConstraints MultiExtractConstraint edge of DatumSurface18
    Sweep38: type Segment, GuideCrv MultiExtract44, Length1 3, Length2 3, Angle 3, DraftDirection Line1
    Sweep39: type Segment, GuideCrv MultiExtract45, Length1 3, Length2 3, Angle 3, DraftDirection Line1
    Extrapol128: ToExtrapol edge of Sweep38, Support Sweep38, Length 10
    Extrapol129: ToExtrapol edge of Sweep39, Support Sweep39, Length 10
    Extrapol130: ToExtrapol edge of Sweep38, Support Extrapol128, Length 10
    Extrapol131: ToExtrapol edge of Sweep39, Support Extrapol129, Length 10
    Extrapol132: ToExtrapol edge of Sweep37, Support Sweep37, Length 0.5
    Extrapol133: ToExtrapol edge of Sweep39, Support Extrapol131, Length 0.5
    Extrapol134: ToExtrapol edge of Sweep38, Support Extrapol130, Length 0.5
    Extrapol135: ToExtrapol edge of Sweep37, Support Extrapol132, Length 0.5
    Trim50: Trimmed (Extrapol134; Extrapol135)
    Trim51: Trimmed (Extrapol133; Trim50)
    DatumCurve1
    Split27: ToCut DatumCurve1, Cutting vertex [face of DatumCurve1 | face of DatumCurve1]
    Split28: ToCut {split ToCut DatumCurve1, Cutting vertex [face of DatumCurve1 | face of DatumCurve1]}, Cutting vertex [face of DatumCurve1 | face of DatumCurve1]
    Split29: ToCut Split28, Cutting vertex [face of DatumCurve1 | face of DatumCurve1]
    Split30: ToCut {split ToCut Split28, Cutting vertex [face of DatumCurve1 | face of DatumCurve1]}, Cutting vertex [face of DatumCurve1 | face of DatumCurve1]
    Sweep40: type Segment, GuideCrv Split30, Length1 3, Length2 3, Angle 3, DraftDirection Line1
    Sweep41: type Segment, GuideCrv Split27, Length1 3, Length2 3, Angle 3, DraftDirection Line1
    Sweep42: type Segment, GuideCrv Split29, Length1 3, Length2 3, Angle 3, DraftDirection Line1
    Extrapol136: ToExtrapol edge of Sweep40, Support Sweep40, Length 0.8
    Extrapol137: ToExtrapol edge of Sweep40, Support Extrapol136, Length 0.8
    Extrapol138: ToExtrapol edge of Sweep41, Support Sweep41, Length 3
    Extrapol139: ToExtrapol edge of Sweep42, Support Sweep42, Length 3
    Extrapol140: ToExtrapol edge of Sweep41, Support Extrapol138, Length 10
    Extrapol141: ToExtrapol edge of Sweep41, Support Extrapol140, Length 10
    Extrapol142: ToExtrapol edge of Sweep42, Support Extrapol139, Length 10
    Extrapol143: ToExtrapol edge of Sweep42, Support Extrapol142, Length 10
    Extrapol144: ToExtrapol edge of Sweep41, Support Extrapol141, Length 10
    Extrapol145: ToExtrapol edge of Sweep42, Support Extrapol143, Length 10
    Trim52: Trimmed (Extrapol144; Extrapol137)
    CurvePar5: Offset edge of Sweep42, Support Extrapol145, Offset2 0, Offset1 8
    Split31: ToCut Extrapol145, Cutting CurvePar5
    Trim53: Trimmed (Split31; Trim52)
    DatumSurface19
    Extrapol146: ToExtrapol edge of DatumSurface19, Support DatumSurface19, Length 3
    Extrapol147: ToExtrapol edge of DatumSurface19, Support Extrapol146, Length 3
  Set7 "MOD"
    MultiExtract46: ListOfMultiExtractConstraints (MultiExtractConstraint face of DatumSurface9; MultiExtractConstraint face of DatumSurface9; MultiExtractConstraint face of DatumSurface9; MultiExtractConstraint face of DatumSurface9; MultiExtractConstraint face of DatumSurface9; MultiExtractConstraint face of DatumSurface9; MultiExtractConstraint face of DatumSurface9)
    MultiExtract47: ListOfMultiExtractConstraints (MultiExtractConstraint face of DatumSurface10; MultiExtractConstraint face of DatumSurface10; MultiExtractConstraint face of DatumSurface10)
    Offset37: Offset MultiExtract46, Length 10
    Offset38: Offset MultiExtract47, Length 10
    MultiExtract48: ListOfMultiExtractConstraints MultiExtractConstraint face of Offset38
    MultiExtract49: ListOfMultiExtractConstraints MultiExtractConstraint face of Offset38
    StUntrimFeature28 "CATStUntrimFeatureName": SpecToUntrim MultiExtract48
    Extrapol148: ToExtrapol edge of StUntrimFeature28, Support StUntrimFeature28, Length 50
    StUntrimFeature29 "CATStUntrimFeatureName": SpecToUntrim MultiExtract49
    Extrapol149: ToExtrapol edge of Offset39, Support Offset39, Length 50
    Intersect8: ToIntersect1 Extrapol221, ToIntersect2 Extrapol149
    Sweep43: type Segment, GuideCrv Intersect8, GuideSurf Extrapol221, Length1 30, Length2 20, Angle 90
    Extrapol150: ToExtrapol edge of Sweep43, Support Sweep43, Length 50
    Extrapol151: ToExtrapol edge of Offset39, Support Offset39, Length 50
    Intersect9: ToIntersect1 Extrapol148, ToIntersect2 Extrapol149
    Sweep44: type Segment, GuideCrv Intersect9, Length1 30, Length2 20, Angle 3, DraftDirection Line1
    Extrapol152: ToExtrapol edge of Sweep44, Support Sweep44, Length 50
    Trim54: Trimmed (Extrapol149; Extrapol152)
    Trim55: Trimmed (Trim54; Extrapol150)
    Offset39: Offset StUntrimFeature29, Length 4
    MultiExtract50: ListOfMultiExtractConstraints MultiExtractConstraint edge [face of ThickSurface2 | face of Split90]
    Sweep45: type Segment, Length1 5, Length2 1, Angle 5, GuideCrv MultiExtract50, DraftDirection Line1
    DatumSurface20
    Plane6: type Normal, Curve edge [face of DatumSurface20 | face of DatumSurface20], RefPoint {point type OnCurve, Support edge [face of DatumSurface20 | face of DatumSurface20], Ratio 0.01}
    Plane7: type Normal, Curve edge [face of DatumSurface20 | face of DatumSurface20], RefPoint {point type OnCurve, Support edge [face of DatumSurface20 | face of DatumSurface20], Ratio 0.99}
    Split32: ToCut DatumSurface20, Cutting Plane7
    Extract3: ExtractElem face of DatumSurface20
    Split33: ToCut Extract3, Cutting Plane6
    MultiExtract51: ListOfMultiExtractConstraints (MultiExtractConstraint face of Sweep83; MultiExtractConstraint face of Offset87; MultiExtractConstraint face of Offset90)
    Plane8: type Normal, Curve edge of Offset90, RefPoint {point type OnCurve, Support edge of Offset90, Length 210.38}
    Split34: ToCut MultiExtract51, Cutting Plane8
    Extrapol153: ToExtrapol edge of DatumSurface20, Support Split33, Length 3
    Extrapol154: ToExtrapol edge of DatumSurface20, Support Extrapol153, Length 3
    Extrapol155: ToExtrapol edge of Split32, Support Extrapol154, Length 20
    Extrapol156: ToExtrapol edge of Split32, Support Extrapol155, Length 20
    Extrapol157: ToExtrapol edge of Split32, Support Extrapol156, Length 20
    Extrapol158: ToExtrapol edge of Split33, Support Extrapol157, Length 20
    Extrapol159: ToExtrapol edge of Split33, Support Extrapol158, Length 20
    Extrapol160: ToExtrapol edge of Split33, Support Extrapol159, Length 20
    Extrapol161: ToExtrapol edge of Split34, Support Split34, Length 120
    Extrapol162: ToExtrapol edge of Split34, Support Extrapol161, Length 120
    Extrapol163: ToExtrapol edge of Split34, Support Extrapol162, Length 120
    Split35: ToCut Extrapol163, Cutting Extrapol160
    Split36: ToCut Extrapol160, Cutting Split35
    Offset40: Offset Split16, Length 0.9
    Intersect10: ToIntersect1 edge [face of Offset90 | face of Offset87], ToIntersect2 edge [face of Offset40 | face of Offset40]
    Plane9: type Normal, Curve edge [face of Offset90 | face of Offset87], RefPoint Intersect10
    Split37: ToCut Split35, Cutting Plane9
    MultiExtract52: ListOfMultiExtractConstraints MultiExtractConstraint face of Sweep83
    MultiExtract53: ListOfMultiExtractConstraints MultiExtractConstraint face of Offset90
    Extrapol164: ToExtrapol edge of MultiExtract53, Support MultiExtract53, Length 30
    Split38: ToCut Offset40, Cutting edge [face of DatumSurface20 | face of DatumSurface20]
    Split39: ToCut Split38, Cutting Extrapol164
    Split40: ToCut Split39, Cutting MultiExtract52
    Split41: ToCut Split40, Cutting edge [face of Offset40 | face of Offset40]
    Extrapol165: ToExtrapol edge of Split35, Support Extrapol164, Length 30
    Split42: ToCut Extrapol165, Cutting {extract ExtractElem face of DatumSurface20}
    Split43: ToCut Split42, Cutting Split41
    Split44: ToCut MultiExtract52, Cutting Split41
    Trim56: Trimmed (edge of Split38; edge of Split42)
    Split45: ToCut Split36, Cutting Trim56
    Join12: Elements (Split44; Split45; Split43; Split41; Split37)
    Sketch2 on Plane12, origin (0, 255.047, 0), H (-1, 0, 0), V (0, 0, 1)
      line L1 (702.6323, 328.6446) -> (732.3943, 355.3241)
      line L2 (732.3943, 355.3241) -> (732.3943, 405.4146)
      vertical: L2 V
    Extrude1: Lim1 59, Lim2 173, Element1 Sketch2
    Offset41: Offset Extrude1, Length 2
    Split46: ToCut Offset40, Cutting Offset41
    Split47: ToCut Split46, Cutting Extrude1
    MultiExtract54: ListOfMultiExtractConstraints (MultiExtractConstraint face of DatumSurface20; MultiExtractConstraint face of DatumSurface20; MultiExtractConstraint face of DatumSurface20)
    MultiExtract55: ListOfMultiExtractConstraints (MultiExtractConstraint face of Offset90; MultiExtractConstraint face of Offset40; MultiExtractConstraint face of Offset87; MultiExtractConstraint face of Sweep83)
    Split48: ToCut MultiExtract55, Cutting Offset41
    Split49: ToCut MultiExtract54, Cutting Offset41
    Split50: ToCut Offset41, Cutting Split47
    Split51: ToCut Split50, Cutting Split48
    Split52: ToCut Split51, Cutting Split49
    Split53: ToCut Extrude1, Cutting Split49
    Split54: ToCut Split53, Cutting Split48
    Split55: ToCut Split54, Cutting Split47
    Trim57: Trimmed (edge [face of Sweep83 | face of Offset40]; edge of Split47)
    Split56: ToCut Split47, Cutting Trim57
    Trim58: Trimmed (edge of Split54; Trim57)
    Split57: ToCut Split48, Cutting Trim58
    Trim59: Trimmed (edge of Split53; edge of Split47)
    Trim60: Trimmed (edge [face of DatumSurface20 | face of DatumSurface20]; Trim59)
    Split58: ToCut Split49, Cutting Trim60
    Split59: ToCut Split56, Cutting Trim60
    Join13: Elements (Split57; Split52; Split59; Split55; Split58)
